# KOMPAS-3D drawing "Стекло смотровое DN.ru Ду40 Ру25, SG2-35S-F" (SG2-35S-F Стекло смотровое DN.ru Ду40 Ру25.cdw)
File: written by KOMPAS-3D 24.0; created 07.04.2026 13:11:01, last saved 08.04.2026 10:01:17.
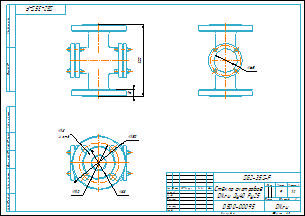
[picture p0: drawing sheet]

Document properties: Автор: Main; Форматы листов документа: A3; Полное имя файла: SG2-35S-F Стекло смотровое DN.ru Ду40 Ру25.m3d; Масса: 9; Наименование: Стекло смотровое DN.ru Ду40 Ру25; Количество листов документа: 1; Примечание: D500-00095

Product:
- Body: Тело 1  | qty 1
    Масса: 7.458074
- Part/product: Стекло смотровое DN.ru Ду40 Ру25  | designation SG2-35S-F
    Масса: 9
    Раздел спецификации: Прочие изделия
    Примечание: D500-00095

Views: Вид 1, Снизу, Проекционный вид 2
Referenced files in D:\DN.ru Аутсерс\Стекло смотровое DN.ru\Стекло смотровое DN.ru SG2-34G-F тип В ГОСТ 21836-2021 Ду100 Ру16, углеродистая сталь, фланцевое\: SG2-34G-F тип В Стекло смотровое DN.ru Ду100 Ру16.m3d, SG2-34G-F тип ВСтекло смотровое DN.ru Ду100 Ру16.cdw
Referenced files in D:\DN.ru Аутсерс\Стекло смотровое DN.ru\SG2-35S-F Стекло смотровое DN.ru Ду40 Ру25\: SG2-35S-F Стекло смотровое DN.ru Ду40 Ру25.m3d
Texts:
  SG2-35S-F
  Стекло смотровое
  DN.ru Ду40 Ру25
  Стекло смотровое DN.ru Ду40 Ру25
  SG2-35S-F Стекло смотровое DN.ru Ду40 Ру25
Dimensions and other numbers on the sheet: 0; 3; 2; 4; 200; 18; 150; 4 отв.; 88; 110; 1:2; 1; 9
